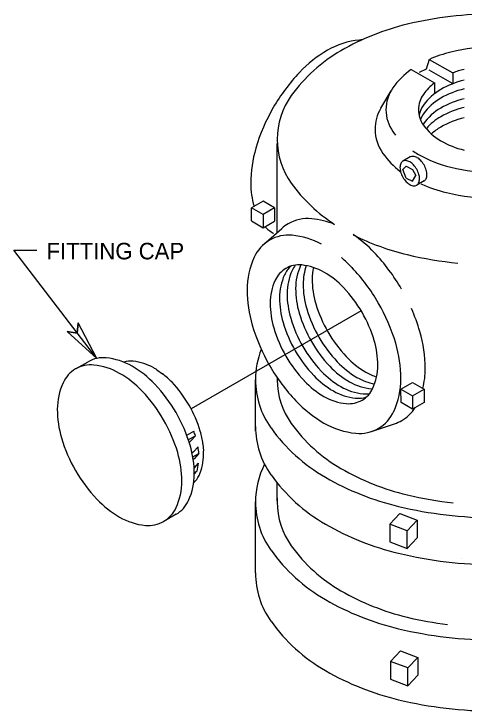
# Model space of a CAD drawing. Extents: x -224.9 to -217.6, y 224 to 234.
# Drawn here: x -224.841 to -223.209, y 227.932 to 230.461 of the extents above; entities that cross this region are included whole.
import ezdxf

# ---------------------------------------------------------------- set-up
doc = ezdxf.new("R2010")
doc.units = 0
for name, color, linetype in [('3', 7, 'Continuous'), ('Default', 7, 'Continuous'), ('DETL-DIMS', 7, 'Continuous'), ('DETL-LINE', 7, 'Continuous'), ('DETL-NOTE', 7, 'Continuous')]:
    doc.layers.add(name, color=color, linetype=linetype)

# ---------------------------------------------------------------- blocks, each defined once
blk = doc.blocks.new('DWG009')
at = {"layer": 'Default'}
for p, q in [((-1.0426, -0.1786), (-1.0426, -0.0086)), ((1.0555, -0.1752), (1.0555, -0.0085)), ((-0.7214, -0.6491), (-0.7364, -0.6066)), ((-0.7214, -0.6151), (-0.7214, -0.6491)), ((-0.6471, -0.7137), (-0.7214, -0.6491)), ((-0.6471, -0.7137), (-0.6729, -0.6408)), ((-0.5779, -0.6986), (-0.5793, -0.6827)), ((-0.5502, -0.7768), (-0.5779, -0.6986)), ((-0.5502, -0.6939), (-0.5502, -0.7768)), ((-0.5037, -0.7299), (-0.5058, -0.7069)), ((-0.476, -0.8081), (-0.5037, -0.7299)), ((-0.375, -0.7689), (-0.3771, -0.7459)), ((-0.3473, -0.8471), (-0.375, -0.7689)), ((-0.3473, -0.7536), (-0.3473, -0.8471)), ((-0.2916, -0.7598), (-0.2916, -0.8591)), ((-0.476, -0.8763), (-0.5502, -0.8416)), ((0.5634, -0.8416), (0.4891, -0.8763))]:
    blk.add_line(p, q, dxfattribs=at)
for centre, radius, start, end in [((0.0066, -1.2132), 1.8125, 90, 103.44948), ((0.0066, -1.2132), 1.8125, 76.55052, 90), ((-0.1359, -0.6173), 1.1998, 103.44948, 120), ((0.1491, -0.6173), 1.1998, 60, 76.55052), ((-0.3528, -0.2417), 0.7661, 120, 144.34287), ((0.366, -0.2417), 0.7661, 35.65713, 60), ((-0.6801, -0.0069), 0.3633, 144.34287, 180), ((0.6932, -0.0069), 0.3633, 0, 35.65713), ((-0.6801, -0.0069), 0.3633, 180, 215.65713), ((0.6932, -0.0069), 0.3633, 324.34287, 360), ((-0.6801, -0.1783), 0.3633, 180, 215.65713), ((-0.3528, 0.2279), 0.7661, 215.65713, 240), ((0.366, 0.2279), 0.7661, 300, 324.34287), ((0.6932, -0.1783), 0.3633, 324.34287, 0), ((-0.3528, 0.0565), 0.7661, 215.65713, 240), ((0.366, 0.0565), 0.7661, 300, 324.34287), ((-0.1359, 0.6035), 1.1998, 240, 256.55052), ((0.1491, 0.6035), 1.1998, 283.44948, 300), ((-0.5427, -0.4784), 0.2906, 193.56979, 215.65713), ((0.0066, 1.1995), 1.8125, 256.55052, 270), ((0.0066, 1.1995), 1.8125, 270, 283.44948), ((0.5559, -0.4784), 0.2906, 324.34287, 346.43021), ((-0.2809, -0.2905), 0.6128, 215.65713, 240), ((-0.1359, 0.4321), 1.1998, 240, 256.55052), ((0.1491, 0.4321), 1.1998, 283.44948, 300), ((0.2941, -0.2905), 0.6128, 300, 324.34287), ((0.0066, 1.028), 1.8125, 256.55052, 270), ((0.0066, 1.028), 1.8125, 270, 283.44948), ((-0.1074, 0.01), 0.9598, 240, 242.52731), ((-0.115, 0.1519), 1.0256, 244.88835, 249.39036), ((0.1206, 0.01), 0.9598, 297.47269, 300), ((-0.1074, 0.01), 0.9598, 247.41975, 256.55052), ((-0.1548, 0.0435), 0.9112, 257.80215, 261.45991), ((0.1206, 0.01), 0.9598, 283.44948, 292.58025), ((0.0066, 0.4867), 1.45, 256.55052, 270), ((0.0066, 0.4867), 1.45, 270, 283.44948)]:
    blk.add_arc(centre, radius, start, end, dxfattribs=at)
blk = doc.blocks.new('SOC')
at = {"layer": '3'}
for p, q in [((-0.242, 0.218), (-0.4, 0.127)), ((-0.325, 0.019), (-0.4, -0.051)), ((-0.325, 0.019), (-0.189, -0.051)), ((-0.325, -0.234), (-0.4, -0.051)), ((-0.189, -0.051), (-0.123, -0.18)), ((-0.325, -0.234), (-0.189, -0.304)), ((-0.189, -0.304), (-0.123, -0.18)), ((0.055, -0.297), (-0.102, -0.388))]:
    blk.add_line(p, q, dxfattribs=at)
at = {"layer": 'Default'}
for centre, radius, start, end in [((-0.191, 0.129), 0.103, 84.3429, 120), ((-0.202, 0.016), 0.217, 60, 84.3429), ((-0.263, -0.091), 0.34, 43.4495, 60), ((-0.244, -0.009), 0.217, 155.6571, 180), ((-0.348, 0.038), 0.103, 120, 155.6571), ((-0.348, 0.038), 0.103, 84.3429, 120), ((-0.359, -0.075), 0.217, 60, 84.3429), ((-0.421, -0.182), 0.34, 43.4495, 60), ((-0.547, -0.301), 0.513, 30, 43.4495), ((-0.389, -0.21), 0.513, 30, 43.4495), ((-0.389, -0.21), 0.513, 16.5505, 30), ((-0.121, -0.009), 0.34, 180, 196.5505), ((0.045, 0.041), 0.513, 196.5505, 210), ((-0.547, -0.301), 0.513, 16.5505, 30), ((-0.223, -0.161), 0.34, 360, 16.5505), ((0.045, 0.041), 0.513, 210, 223.4495), ((-0.258, -0.251), 0.217, 335.6571, 0), ((-0.38, -0.251), 0.34, 360, 16.5505), ((0.004, -0.208), 0.103, 300, 335.6571), ((-0.1, -0.161), 0.217, 335.6571, 0), ((-0.081, -0.079), 0.34, 223.4495, 240), ((-0.142, -0.185), 0.217, 240, 264.3429), ((-0.154, -0.298), 0.103, 264.3429, 300), ((-0.154, -0.298), 0.103, 300, 335.6571)]:
    blk.add_arc(centre, radius, start, end, dxfattribs=at)

msp = doc.modelspace()

# ---------------------------------------------------------------- linework, layer by layer
at = {"layer": 'DETL-DIMS'}
for p, q in [((-224.5408, 229.2116), (-224.8414, 229.6037)), ((-224.8414, 229.6037), (-224.7582, 229.6037)), ((-223.582, 229.3841), (-224.1986, 229.0281)), ((-224.6115, 229.3036), (-224.608, 229.3403)), ((-224.5408, 229.2116), (-224.608, 229.3403)), ((-224.5408, 229.2116), (-224.648, 229.3096)), ((-224.648, 229.3096), (-224.6115, 229.3036))]:
    msp.add_line(p, q, dxfattribs=at)
msp.add_lwpolyline([(-224.648, 229.3096), (-224.5408, 229.2116), (-224.608, 229.3403), (-224.6115, 229.3036)], close=True, dxfattribs=at)
at = {"layer": 'DETL-LINE'}
for p, q in [((-223.3347, 230.2959), (-223.3467, 230.2602)), ((-223.3347, 230.2959), (-223.2499, 230.2469)), ((-223.4002, 230.2594), (-223.316, 230.2108)), ((-223.3467, 230.2602), (-223.371, 230.2483)), ((-223.3362, 230.2586), (-223.2514, 230.2097)), ((-223.2499, 230.2469), (-223.2499, 230.2106)), ((-223.316, 230.2108), (-223.316, 230.1718)), ((-223.5109, 230.1186), (-223.4734, 230.1826)), ((-223.8863, 229.6686), (-223.8863, 229.9911)), ((-223.9374, 229.7821), (-223.9793, 229.7582)), ((-223.8957, 229.7578), (-223.9374, 229.7821)), ((-223.9796, 229.7099), (-223.9793, 229.7582)), ((-223.9377, 229.7339), (-223.9793, 229.7582)), ((-223.8957, 229.7578), (-223.9377, 229.7339)), ((-223.8957, 229.7578), (-223.896, 229.7095)), ((-223.9377, 229.7339), (-223.9379, 229.6856)), ((-223.9796, 229.7099), (-223.9379, 229.6856)), ((-223.9379, 229.6856), (-223.896, 229.7095)), ((-223.9361, 229.6245), (-223.8699, 229.6831)), ((-223.9652, 228.9482), (-223.9652, 229.1343)), ((-223.8863, 229.1405), (-223.8863, 229.1413)), ((-223.4376, 229.1), (-223.3959, 229.1243)), ((-223.3959, 229.1243), (-223.354, 229.1004)), ((-223.4376, 229.1), (-223.3957, 229.076)), ((-223.4374, 229.0517), (-223.4376, 229.1)), ((-223.3957, 229.076), (-223.354, 229.1004)), ((-223.354, 229.1004), (-223.3538, 229.0521)), ((-223.3957, 229.076), (-223.3954, 229.0277)), ((-223.3954, 229.0277), (-223.4374, 229.0517)), ((-223.3538, 229.0521), (-223.3954, 229.0277)), ((-223.5446, 228.9464), (-223.4608, 228.9745)), ((-223.8861, 228.6946), (-223.8861, 228.7607)), ((-223.9652, 228.4332), (-223.9652, 228.6907)), ((-223.478, 228.6105), (-223.4417, 228.6487)), ((-223.4417, 228.6487), (-223.3792, 228.6247)), ((-223.478, 228.6105), (-223.4777, 228.5461)), ((-223.4155, 228.5866), (-223.478, 228.6105)), ((-223.4155, 228.5866), (-223.3792, 228.6247)), ((-223.3792, 228.6247), (-223.3788, 228.5604)), ((-223.4151, 228.5222), (-223.4155, 228.5866)), ((-223.3788, 228.5604), (-223.4151, 228.5222)), ((-223.4777, 228.5461), (-223.4151, 228.5222)), ((-223.2188, 228.4868), (-223.2188, 228.4868)), ((-223.4754, 228.1126), (-223.4391, 228.1508)), ((-223.4391, 228.1508), (-223.3766, 228.1268)), ((-223.4128, 228.0887), (-223.3766, 228.1268)), ((-223.3766, 228.1268), (-223.3762, 228.0625)), ((-223.4128, 228.0887), (-223.4754, 228.1126)), ((-223.4754, 228.1126), (-223.4751, 228.0482)), ((-223.4125, 228.0243), (-223.4128, 228.0887)), ((-223.4751, 228.0482), (-223.4125, 228.0243)), ((-223.3762, 228.0625), (-223.4125, 228.0243))]:
    msp.add_line(p, q, dxfattribs=at)
for centre, radius, start, end in [((-223.0979, 229.0997), 1.3612, 90, 103.4495), ((-223.2049, 229.5473), 0.901, 103.4495, 120), ((-223.5599, 230.08), 0.2877, 95.6571, 120), ((-223.5748, 230.2305), 0.1364, 91.0477, 95.6571), ((-223.3678, 229.8293), 0.5753, 120, 144.3429), ((-223.4785, 229.939), 0.4505, 120, 136.5505), ((-223.1514, 229.8843), 0.4505, 103.4495, 113.9984), ((-223.0979, 229.6606), 0.6806, 90, 103.4495), ((-223.3114, 229.7807), 0.6806, 136.5505, 150), ((-223.2329, 230.0254), 0.2877, 125.5618, 144.3429), ((-223.1354, 229.9531), 0.3154, 103.4495, 111.2855), ((-223.1354, 229.9138), 0.3154, 103.4495, 120), ((-223.1924, 230.0518), 0.2014, 127.8686, 144.3429), ((-223.3557, 230.1135), 0.1364, 144.3429, 180), ((-223.1924, 230.0125), 0.2014, 120, 144.3429), ((-223.1354, 229.8822), 0.3154, 103.4495, 120), ((-223.6136, 230.0057), 0.2728, 144.3429, 180), ((-223.2784, 230.1135), 0.0955, 144.3429, 180), ((-223.1924, 229.9809), 0.2014, 120, 144.3429), ((-223.1354, 229.8465), 0.3154, 103.4495, 120), ((-223.3114, 229.7807), 0.6806, 150, 163.4495), ((-223.2784, 230.0742), 0.0955, 144.3429, 168.1188), ((-223.1924, 229.9452), 0.2014, 120, 144.3429), ((-223.1354, 229.8149), 0.3154, 103.4495, 120), ((-223.3815, 230.0427), 0.15, 149.5892, 180), ((-223.3557, 230.1135), 0.1364, 180, 215.6571), ((-223.2784, 230.1135), 0.0955, 180, 215.6571), ((-223.2784, 230.0427), 0.0955, 144.3429, 158.2145), ((-223.1924, 229.9137), 0.2014, 120, 139.4934), ((-223.1354, 229.7772), 0.3154, 103.4495, 120), ((-223.2784, 230.007), 0.0955, 144.3429, 146.0731), ((-223.1924, 230.1753), 0.2014, 215.6571, 240), ((-223.1924, 229.8759), 0.2014, 120, 131.9831), ((-223.3815, 230.0427), 0.15, 180, 215.6571), ((-223.2329, 230.2017), 0.2877, 215.6571, 218.8205), ((-223.6136, 230.0057), 0.2728, 180, 215.6571), ((-223.1354, 230.274), 0.3154, 240, 256.5505), ((-223.532, 229.8463), 0.4505, 163.4495, 180), ((-223.2464, 230.1396), 0.3164, 215.6571, 232.2881), ((-223.2329, 230.2017), 0.2877, 235.4315, 240), ((-223.1514, 230.3427), 0.4505, 240, 256.5505), ((-223.0979, 230.5665), 0.6806, 256.5505, 270), ((-223.6948, 229.8463), 0.2877, 180, 196.7482), ((-223.3678, 230.182), 0.5753, 215.6571, 237.3569), ((-223.1568, 230.2948), 0.4956, 245.1657, 256.5505), ((-223.0979, 230.5409), 0.7487, 256.5505, 270), ((-223.7755, 229.5763), 0.1425, 84.3429, 120), ((-223.791, 229.419), 0.3006, 67.9324, 84.3429), ((-223.7755, 229.5763), 0.1425, 120, 131.4926), ((-223.8326, 229.7839), 0.1364, 223.8213, 240), ((-223.8326, 229.7839), 0.1364, 240, 240.4783), ((-223.8458, 229.5223), 0.1364, 120, 155.6571), ((-223.8458, 229.5223), 0.1364, 84.3429, 120), ((-223.8607, 229.3718), 0.2877, 61.9986, 84.3429), ((-223.2049, 230.4641), 0.901, 243.2271, 256.5505), ((-223.8761, 229.2717), 0.4708, 43.4495, 55.6439), ((-224.0507, 229.1063), 0.7112, 30.0921, 43.4495), ((-223.708, 229.46), 0.2877, 155.6571, 180), ((-223.9421, 229.2308), 0.4505, 43.4495, 50.2149), ((-223.0979, 230.9117), 1.3612, 256.5505, 264.3721), ((-223.8071, 229.4554), 0.0955, 120, 155.6571), ((-223.773, 229.475), 0.0955, 131.8812, 155.6571), ((-223.8071, 229.4554), 0.0955, 84.3429, 120), ((-223.7457, 229.4908), 0.0955, 141.7855, 155.6571), ((-223.6183, 229.465), 0.2014, 155.6571, 180), ((-223.7148, 229.5086), 0.0955, 153.9269, 155.6571), ((-223.8175, 229.35), 0.2014, 60, 84.3429), ((-223.591, 229.4808), 0.2014, 160.5066, 180), ((-223.5583, 229.4997), 0.2014, 168.0169, 180), ((-224.1091, 229.0726), 0.6806, 30, 43.4495), ((-223.6766, 229.4314), 0.2014, 155.6571, 180), ((-223.6492, 229.4471), 0.2014, 155.6571, 180), ((-223.8745, 229.2513), 0.3154, 43.4495, 60), ((-223.7106, 229.4117), 0.2014, 155.6571, 180), ((-223.4443, 229.4997), 0.3154, 180, 196.5505), ((-223.5043, 229.465), 0.3154, 180, 196.5505), ((-223.477, 229.4808), 0.3154, 180, 196.5505), ((-223.9914, 229.1405), 0.4764, 30, 43.4495), ((-223.5451, 229.46), 0.4505, 180, 196.5505), ((-223.5352, 229.4471), 0.3154, 180, 196.5505), ((-223.5966, 229.4117), 0.3154, 180, 196.5505), ((-223.5626, 229.4314), 0.3154, 180, 196.5505), ((-224.1091, 229.0726), 0.6806, 16.5505, 30), ((-223.3226, 229.5267), 0.4764, 196.5505, 210), ((-223.2899, 229.5456), 0.4764, 196.5505, 210), ((-224.0507, 229.1063), 0.7112, 16.5505, 23.6908), ((-223.3499, 229.5109), 0.4764, 196.5505, 210), ((-223.9914, 229.1405), 0.4764, 16.5505, 30), ((-223.4082, 229.4773), 0.4764, 196.5505, 210), ((-223.3808, 229.493), 0.4764, 196.5505, 210), ((-223.3245, 229.5255), 0.6806, 196.5505, 210), ((-223.4422, 229.4576), 0.4764, 196.5505, 210), ((-223.3226, 229.5267), 0.4764, 210, 223.4495), ((-223.2899, 229.5456), 0.4764, 210, 223.4495), ((-223.8202, 229.1748), 0.4708, 360, 16.5505), ((-223.3499, 229.5109), 0.4764, 210, 223.4495), ((-223.8371, 229.1864), 0.3154, 360, 16.5505), ((-223.8886, 229.1381), 0.4505, 0, 16.5505), ((-223.6652, 229.1343), 0.3001, 158.4826, 180), ((-223.4082, 229.4773), 0.4764, 210, 223.4495), ((-223.3808, 229.493), 0.4764, 210, 223.4495), ((-223.4422, 229.4576), 0.4764, 210, 223.4495), ((-223.4068, 229.4348), 0.3154, 223.4495, 240), ((-223.3245, 229.5255), 0.6806, 210, 223.4495), ((-223.4395, 229.4159), 0.3154, 223.4495, 240), ((-223.7231, 229.1864), 0.2014, 335.6571, 360), ((-223.4978, 229.3823), 0.3154, 223.4495, 240), ((-223.4668, 229.4001), 0.3154, 223.4495, 240), ((-223.4638, 229.3361), 0.2014, 240, 251.9831), ((-223.65, 229.1748), 0.3006, 346.137, 360), ((-223.6652, 229.1343), 0.3001, 180, 215.6571), ((-223.6136, 229.1343), 0.2728, 178.6895, 180), ((-223.6136, 229.1343), 0.2728, 180, 215.6571), ((-223.5251, 229.3665), 0.3154, 223.4495, 240), ((-223.4965, 229.3172), 0.2014, 240, 259.4934), ((-223.7257, 229.1381), 0.2877, 335.6571, 360), ((-223.5592, 229.3468), 0.3154, 223.4495, 240), ((-223.5548, 229.2835), 0.2014, 240, 264.3429), ((-223.5239, 229.3014), 0.2014, 240, 264.3429), ((-223.5821, 229.2678), 0.2014, 240, 264.3429), ((-223.6266, 229.1427), 0.0955, 300, 335.6571), ((-223.5652, 229.1782), 0.0955, 264.3429, 278.2145), ((-223.5343, 229.196), 0.0955, 264.3429, 266.0731), ((-223.4916, 229.3673), 0.4505, 223.4495, 240), ((-223.6162, 229.2481), 0.2014, 240, 264.3429), ((-223.6266, 229.1427), 0.0955, 264.3429, 300), ((-223.5925, 229.1624), 0.0955, 264.3429, 288.1188), ((-223.506, 229.1096), 0.1425, 300, 327.7484), ((-223.5879, 229.0758), 0.1364, 300, 335.6571), ((-223.506, 229.1096), 0.1425, 288.5074, 300), ((-223.6652, 228.9643), 0.3001, 180, 215.6571), ((-223.3948, 229.3282), 0.6328, 215.6571, 240), ((-223.3678, 229.3106), 0.5753, 215.6571, 240), ((-223.573, 229.2263), 0.2877, 240, 264.3429), ((-223.5879, 229.0758), 0.1364, 264.3429, 300), ((-223.6652, 228.6907), 0.3001, 152.8788, 180), ((-223.2049, 229.5927), 0.901, 240, 256.5505), ((-223.3948, 229.1583), 0.6328, 215.6571, 240), ((-223.2156, 229.6385), 0.9911, 240, 256.5505), ((-223.6136, 228.6907), 0.2728, 177.1827, 180), ((-223.0979, 230.0402), 1.3612, 256.5505, 263.681), ((-223.6652, 228.6907), 0.3001, 180, 215.6571), ((-223.6136, 228.6907), 0.2728, 180, 215.6571), ((-223.0979, 230.1308), 1.4973, 256.5505, 270), ((-223.2156, 229.4686), 0.9911, 240, 256.5505), ((-223.3678, 228.867), 0.5753, 215.6571, 240), ((-223.3948, 228.8847), 0.6328, 215.6571, 240), ((-223.0979, 229.9609), 1.4973, 256.5505, 270), ((-223.6652, 228.4332), 0.3001, 180, 215.6571), ((-223.2049, 229.1491), 0.901, 240, 256.5505), ((-223.2156, 229.1949), 0.9911, 240, 256.5505), ((-223.3948, 228.6271), 0.6328, 215.6571, 240), ((-223.0979, 229.5967), 1.3612, 256.5505, 262.8104), ((-223.0979, 229.6873), 1.4973, 256.5505, 270), ((-223.2156, 228.9374), 0.9911, 240, 256.5505), ((-223.0979, 229.4297), 1.4973, 256.5505, 270)]:
    msp.add_arc(centre, radius, start, end, dxfattribs=at)

# ---------------------------------------------------------------- block references
at = {"layer": 'DETL-LINE', "xscale": 0.16897595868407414, "yscale": 0.16897595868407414}
msp.add_blockref('SOC', (-223.3632, 229.9052), dxfattribs=at)
at = {"layer": 'DETL-LINE', "xscale": 0.30415672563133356, "yscale": 0.30415672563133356, "rotation": 119.99999999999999}
msp.add_blockref('DWG009', (-224.459, 228.8938), dxfattribs=at)

# ---------------------------------------------------------------- texts
at = {"layer": 'DETL-NOTE'}
msp.add_text('FITTING CAP', height=0.06, dxfattribs=at).set_placement((-224.7232, 229.5707))

doc.saveas('drawing.dxf')
